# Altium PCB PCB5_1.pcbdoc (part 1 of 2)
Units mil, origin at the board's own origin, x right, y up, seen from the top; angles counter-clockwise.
Board outline 4312.83 x 4315.15 mil, 4 copper layers (Top Layer, Inner1, Inner2, Bottom Layer); 84 components, 70 nets, 244 pads, 79 vias.
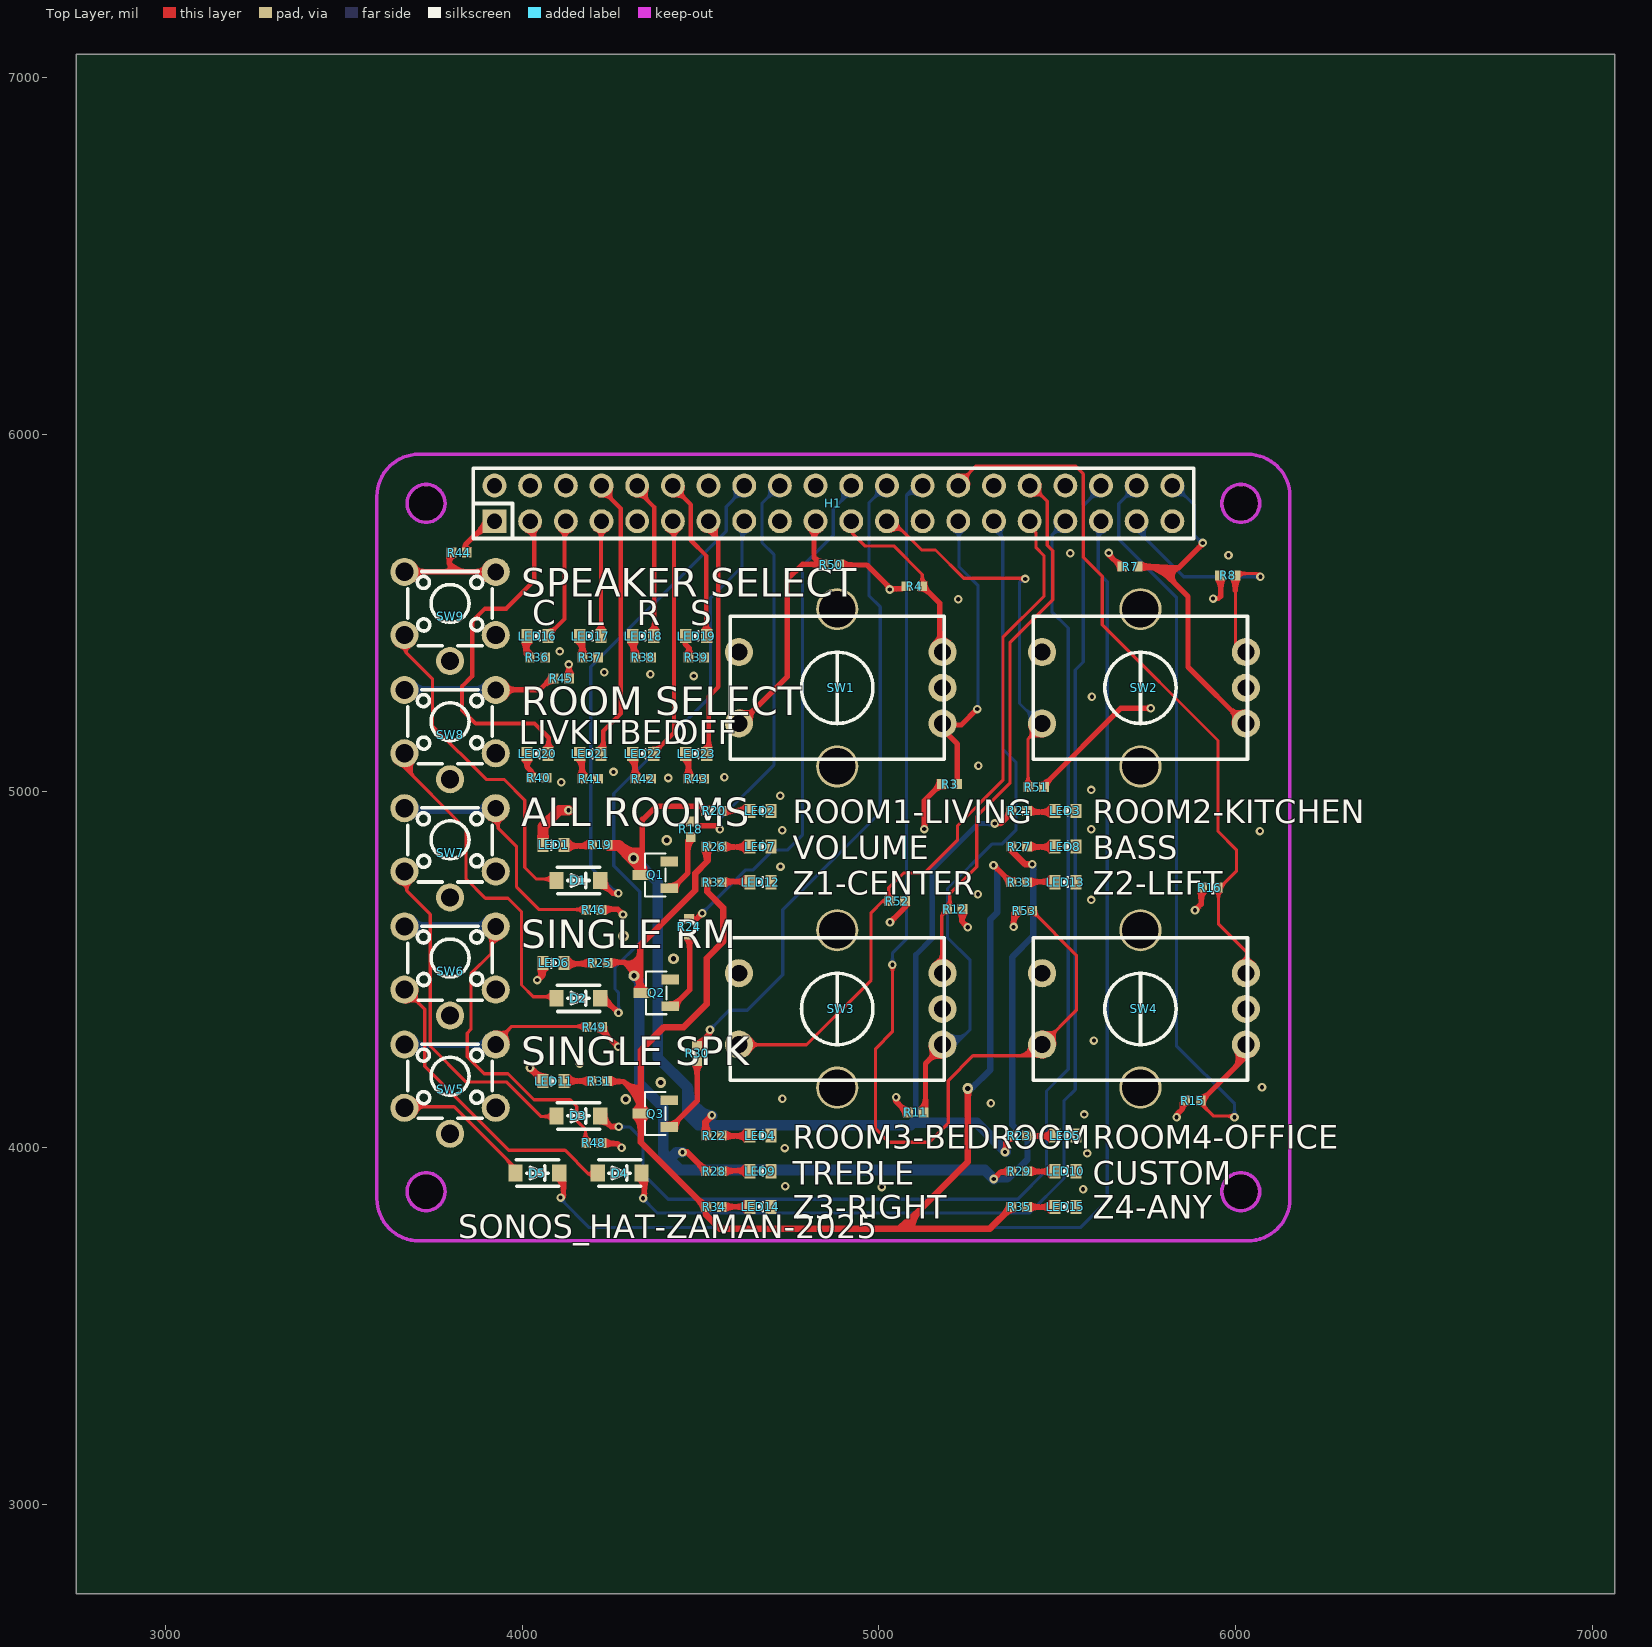
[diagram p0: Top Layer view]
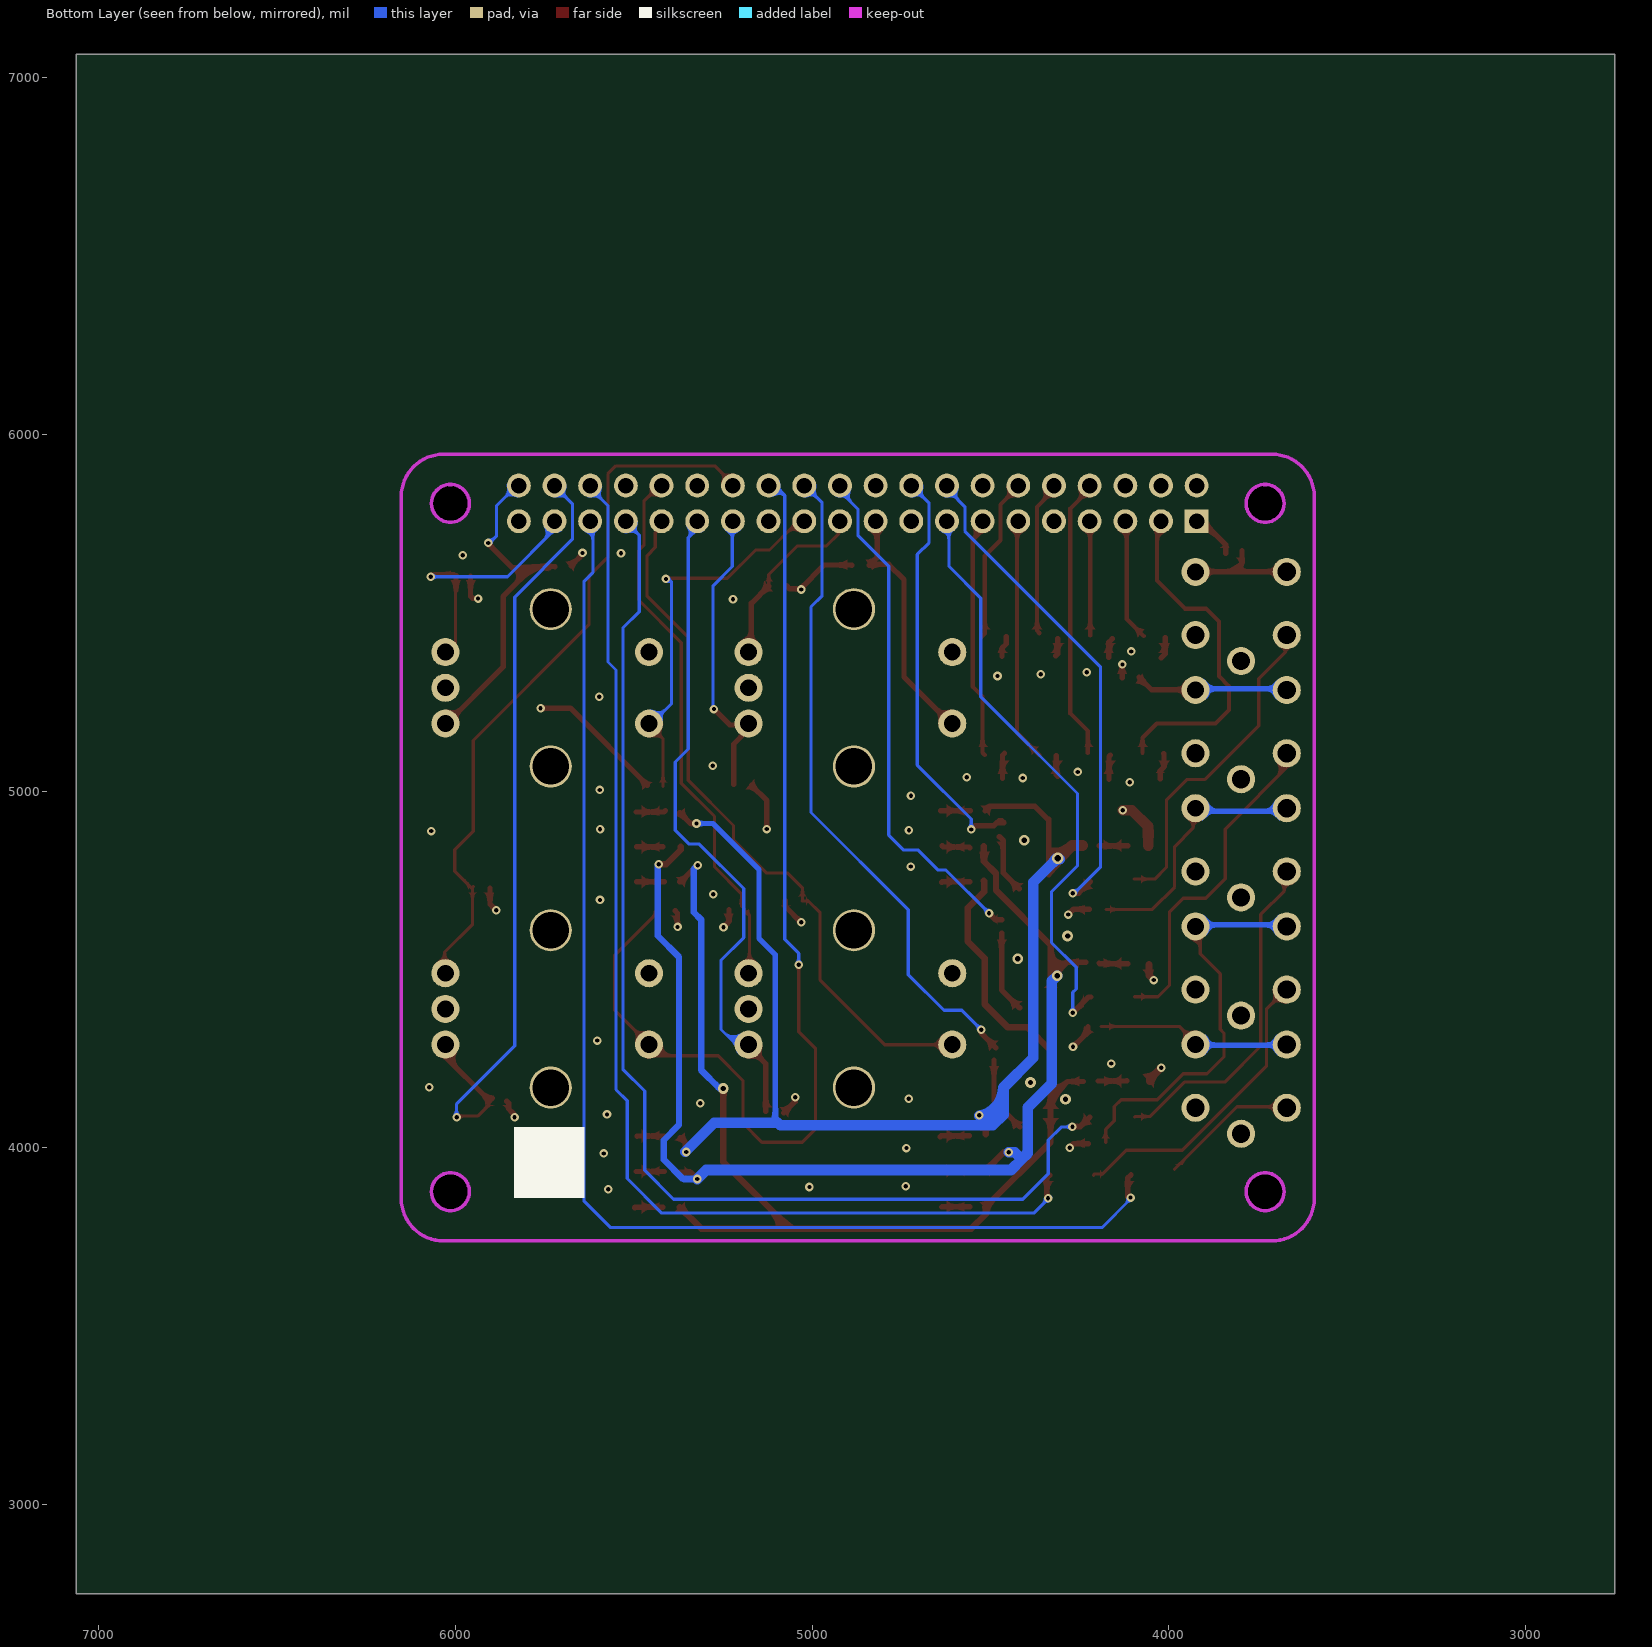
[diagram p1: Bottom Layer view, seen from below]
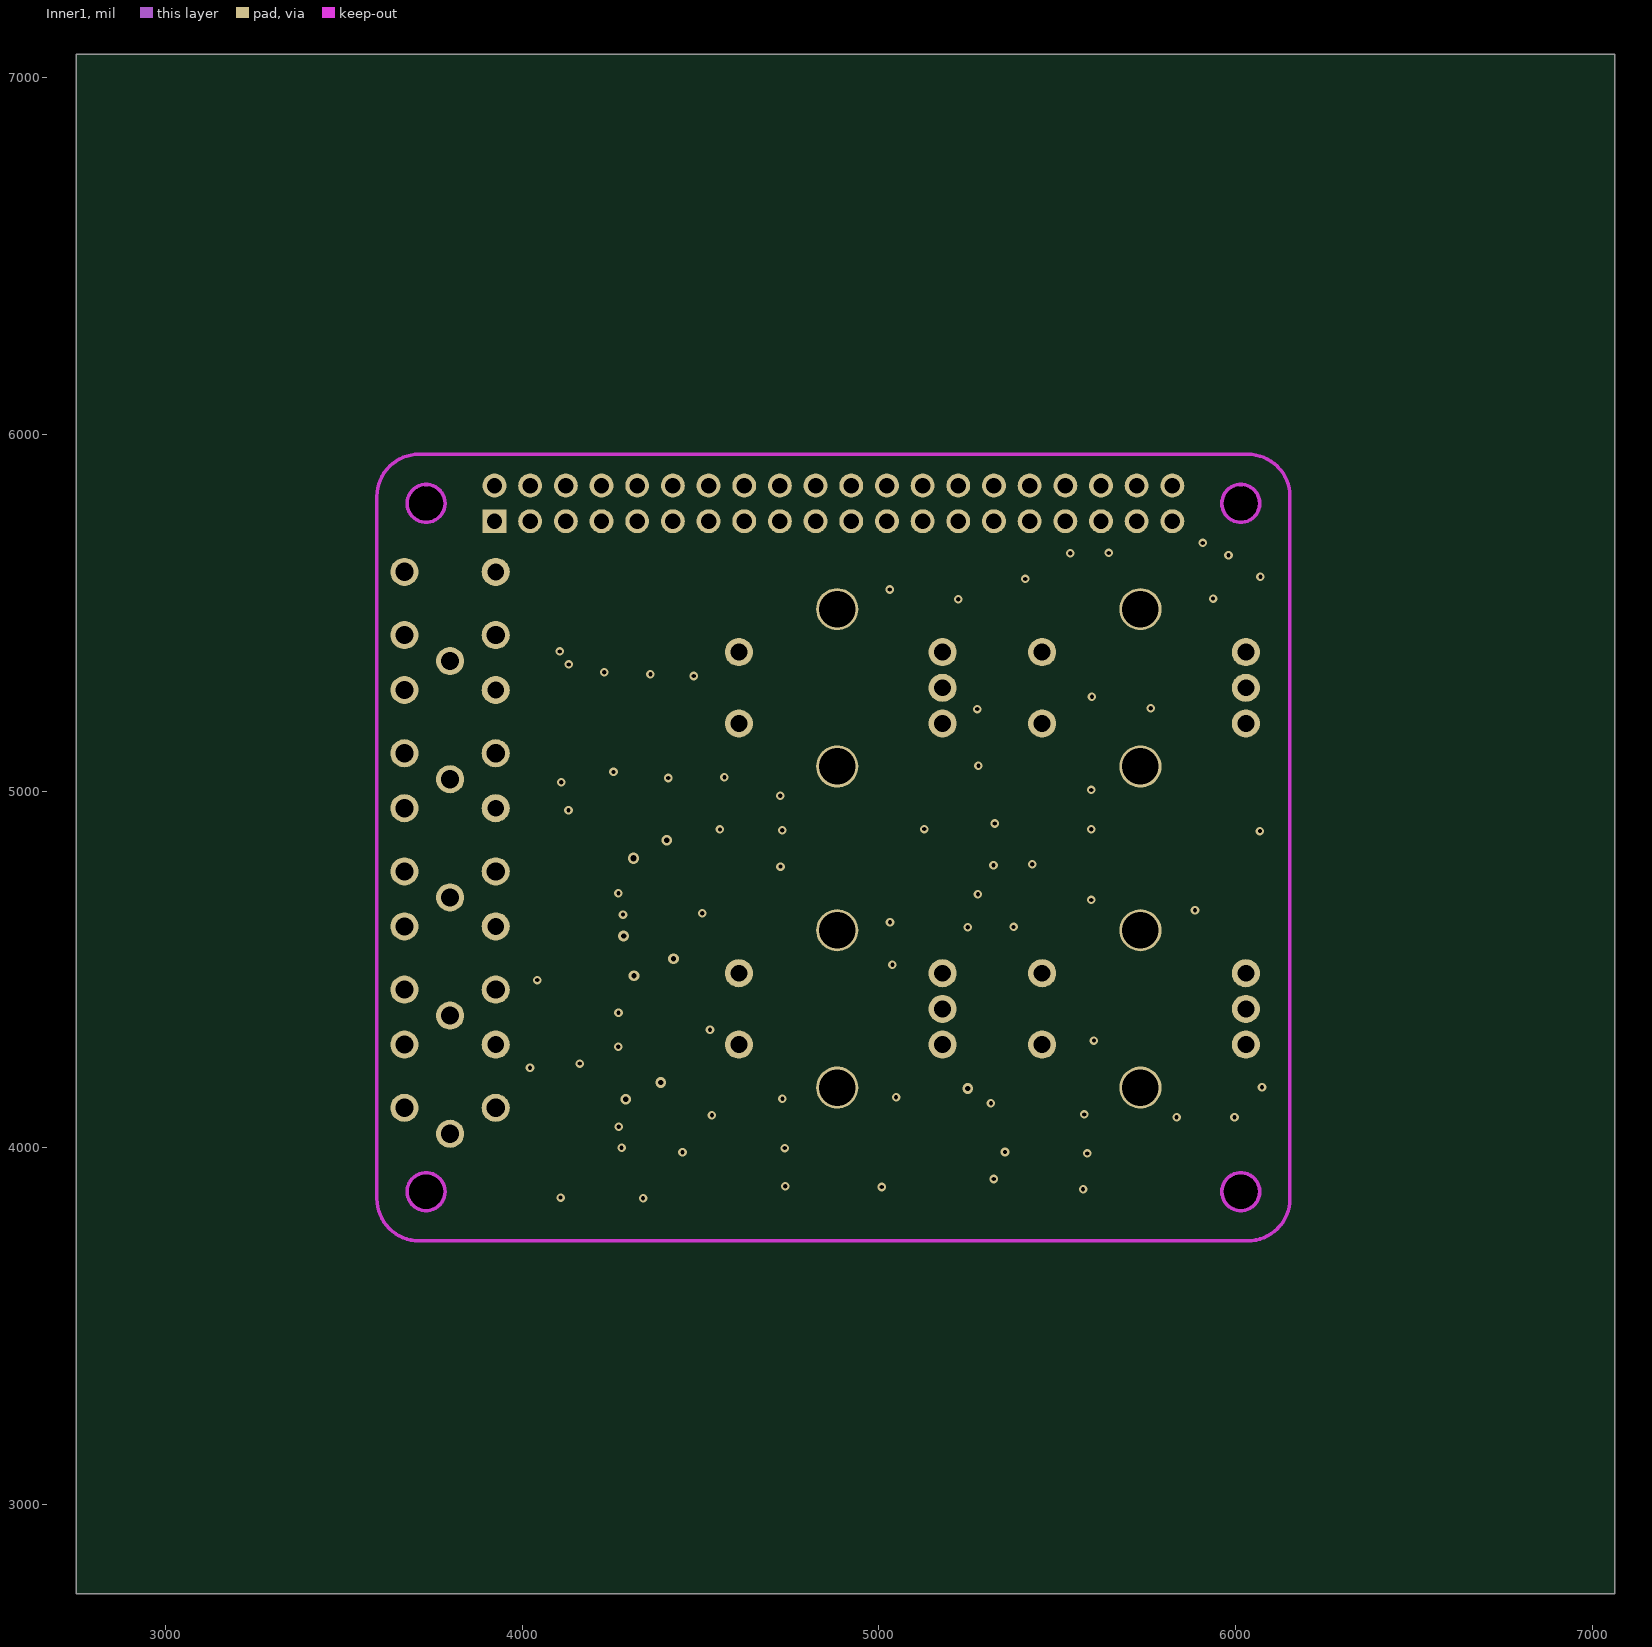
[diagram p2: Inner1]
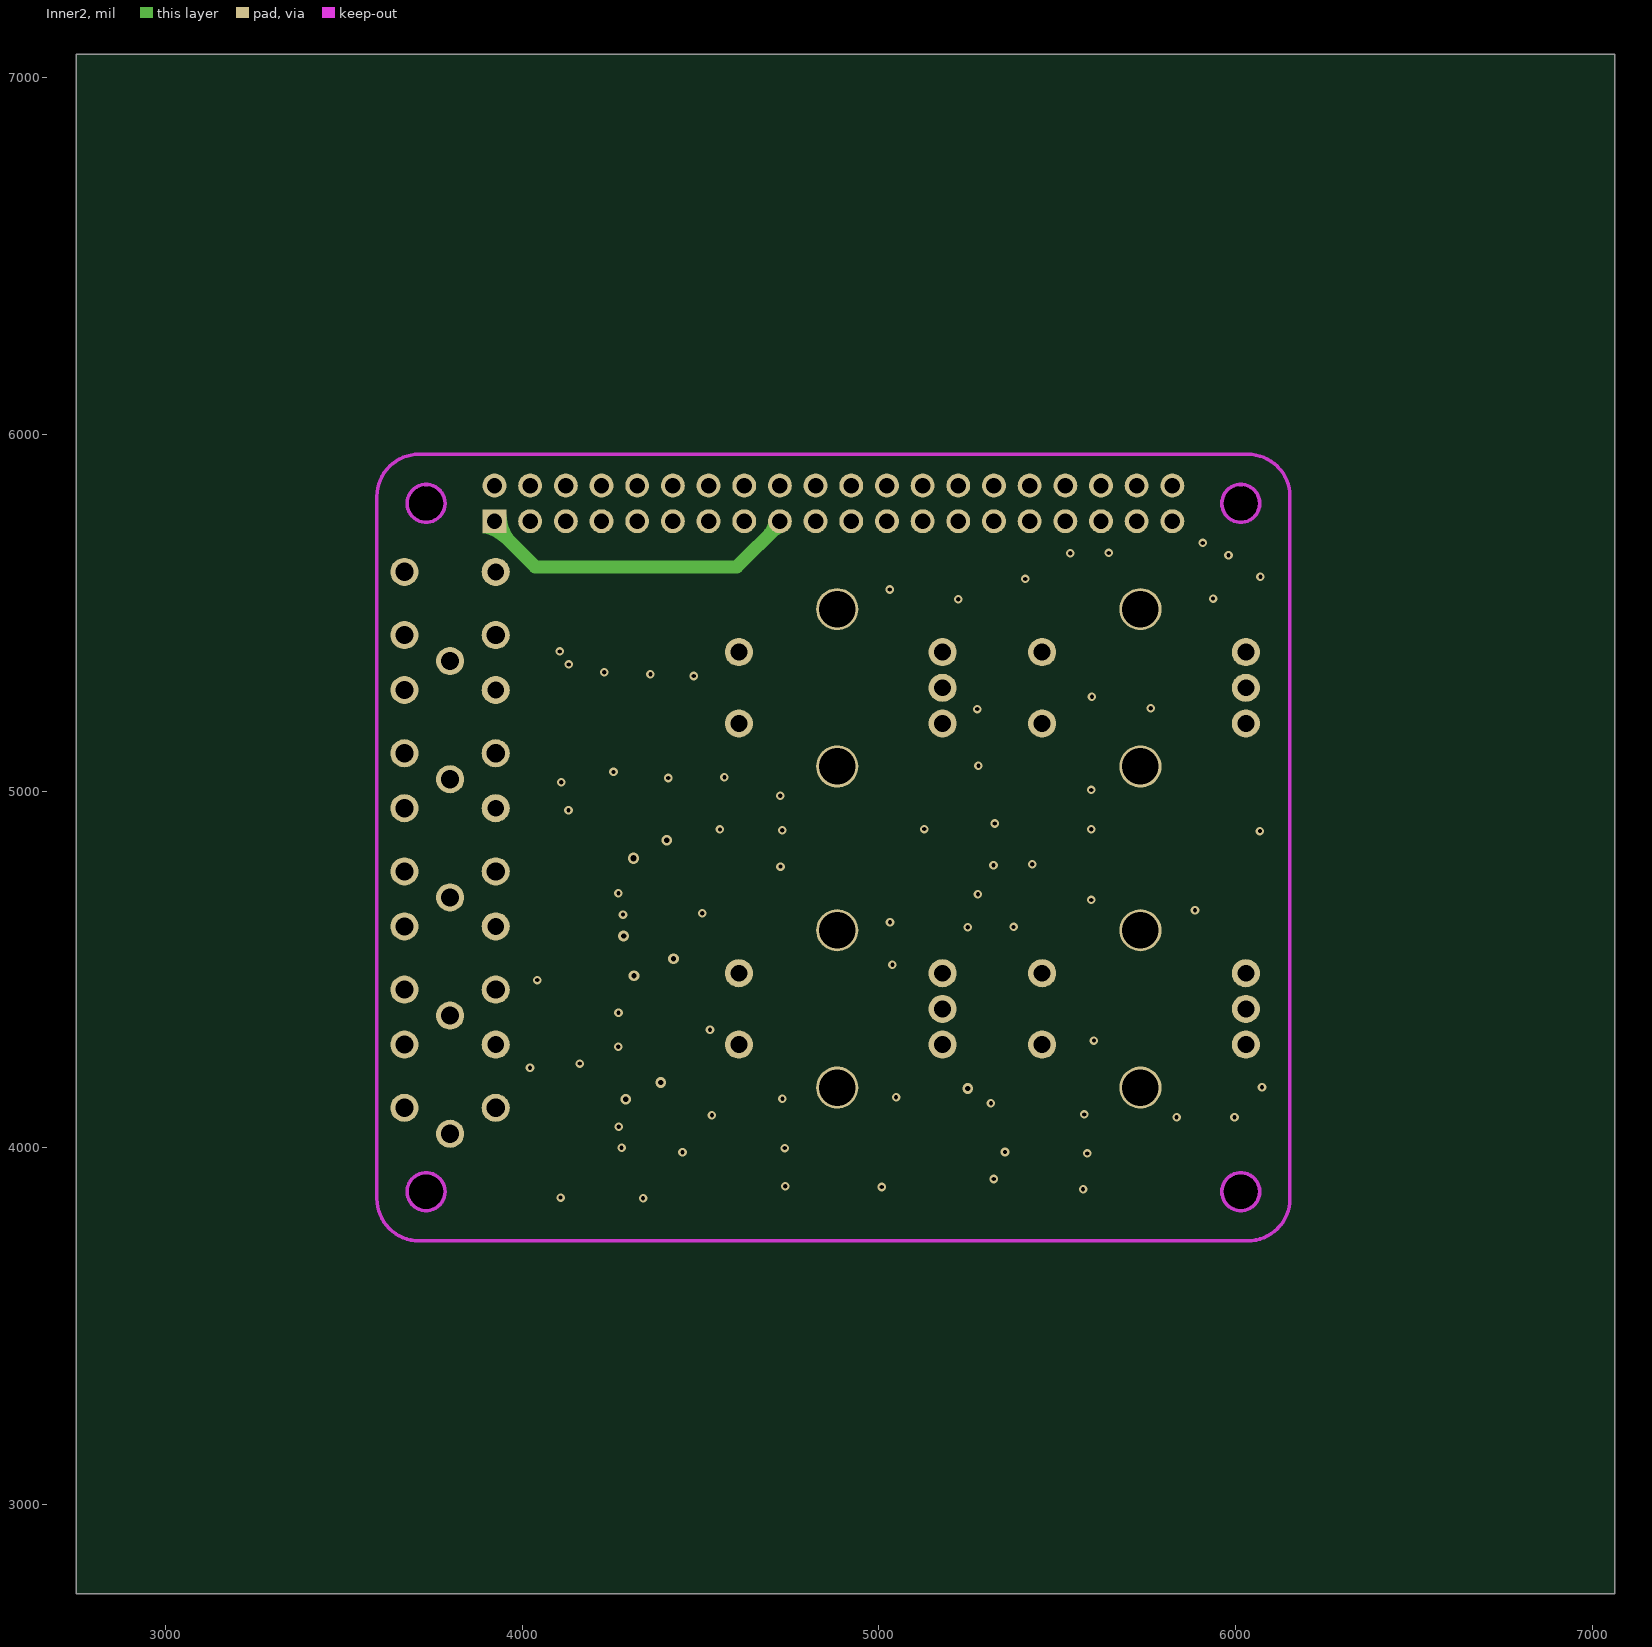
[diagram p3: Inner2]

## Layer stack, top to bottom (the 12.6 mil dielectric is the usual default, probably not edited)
Top Layer: signal copper (thickness not stored)
Dielectric: dielectric 12.6, FR-4, Dk 4.8
Inner1: signal copper (thickness not stored)
Dielectric: dielectric 12.6, FR-4, Dk 4.8
Inner2: signal copper (thickness not stored)
Dielectric: dielectric 12.6, FR-4, Dk 4.8
Bottom Layer: signal copper (thickness not stored)

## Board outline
7062.83,2750 2750,2750 2750,7065.15 7062.83,7065.15
cut-out: 3783.73,3877.07 ccw(c3730.58,3877.07) 3677.43,3877.07 ccw(c3730.58,3877.07)
cut-out: 3783.73,5806.2 ccw(c3730.58,5806.2) 3677.43,5806.2 ccw(c3730.58,5806.2)
cut-out: 6067.2,3877.07 ccw(c6014.05,3876.85) 5960.9,3877.07 ccw(c6014.05,3877.29)
cut-out: 6067.2,5806.2 ccw(c6014.05,5805.98) 5960.9,5806.2 ccw(c6014.05,5806.42)

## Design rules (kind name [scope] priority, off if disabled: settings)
BoardOutlineClearance copperThickness1oz [All] p0: genericclearance=10 ignorepadtopadclearanceinfootprint=FALSE except(0: Arc-SplitContinuation Track-SplitContinuation SMDPad-SplitContinuation THPad-SplitContinuation Via-SplitContinuation Fill-SplitContinuation Poly-SplitContinuation Region-SplitContinuation Text-SplitContinuation; 6: Track-CutoutEdge SMDPad-CutoutEdge THPad-CutoutEdge Via-CutoutEdge Region-CutoutEdge; 11.8: Track-OutlineEdge SMDPad-OutlineEdge THPad-OutlineEdge Via-OutlineEdge Fill-OutlineEdge Region-OutlineEdge Poly-OutlineEdge Text-OutlineEdge Fill-CutoutEdge)
BoardOutlineClearance copperThickness2oz [All] p0: genericclearance=10 ignorepadtopadclearanceinfootprint=FALSE except(0: Arc-SplitContinuation Track-SplitContinuation SMDPad-SplitContinuation THPad-SplitContinuation Via-SplitContinuation Fill-SplitContinuation Poly-SplitContinuation Region-SplitContinuation Text-SplitContinuation; 6: Track-CutoutEdge SMDPad-CutoutEdge THPad-CutoutEdge Via-CutoutEdge Region-CutoutEdge; 11.8: Track-OutlineEdge SMDPad-OutlineEdge THPad-OutlineEdge Via-OutlineEdge Fill-OutlineEdge Region-OutlineEdge Poly-OutlineEdge Text-OutlineEdge Fill-CutoutEdge)
Clearance copperThickness1oz [(InNet('GND') OR InNet('CLK_VOL') OR InNet('DT_VOL') OR InNet('+3.3V') OR InNet('+5V') OR InNet('DT_TREB') OR InNet('CLK_TREB') OR InNet('SW_BASS') OR InNet('DT_BASS') OR InNet('CLK_BASS') OR InNet('SW_TREB') OR InNet('SW_VOL') OR InNet('DT_EXTRA') OR InNet('CLK_EXTRA') OR InNet('SW_EXTRA') OR InNet('ROOM3_LED') OR InNet('ROOM4_LED') OR InNet('ALL_ROOM_LED') OR InNet('SINGLE_ROOM_LED') OR InNet('SINGLE_SPK_LED') OR InNet('SPK1_LED') OR InNet('SPK2_LED') OR InNet('SPK3_LED') OR InNet('SPK4_LED') OR InNet('ROOM1_LED') OR InNet('ROOM2_LED') OR InNet('$2N567') OR InNet('$2N579') OR InNet('$2N581') OR InNet('$2N585') OR InNet('$2N583') OR InNet('$2N1097') OR InNet('$2N1109') OR InNet('$2N1111') OR InNet('$2N1113') OR InNet('$2N1115') OR InNet('$2N1627') OR InNet('$2N1639') OR InNet('$2N1641') OR InNet('$2N1643') OR InNet('$2N1645') OR InNet('$2N2275') OR InNet('$2N2279') OR InNet('$2N2284') OR InNet('$2N2289') OR InNet('$2N2294') OR InNet('$2N2299') OR InNet('$2N2307') OR InNet('$2N2312') OR InNet('$2N553') OR InNet('$2N557') OR InNet('$2N1083') OR InNet('$2N1087') OR InNet('$2N1613') OR InNet('$2N1617') OR InNet('SW_ALL_ROOM') OR InNet('SW_SINGLE_ROOM') OR InNet('SW_SINGLE_SPK') OR InNet('SW_CHG_SPK') OR InNet('SW_CHG_ROOM') OR InNet('$2N6344') OR InNet('$2N6573') OR InNet('$2N6348') OR InNet('$2N6576') OR InNet('$2N6353') OR InNet('$2N6578') OR InNet('$2N6363') OR InNet('$2N6582') OR InNet('$2N6358') OR InNet('$2N6580'))] p1: gap=7 ignorepadtopadclearanceinfootprint=FALSE except(4: Track-Track; 6: Track-SMDPad SMDPad-SMDPad Track-THPad SMDPad-THPad THPad-THPad Track-Via SMDPad-Via THPad-Via Via-Via SMDPad-Fill THPad-Fill Via-Fill Fill-Fill Track-Region SMDPad-Region THPad-Region Via-Region Region-Region Track-Poly SMDPad-Poly THPad-Poly Via-Poly Fill-Poly Region-Poly Poly-Poly Track-Text SMDPad-Text THPad-Text Via-Text Fill-Text Region-Text Poly-Text Text-Text; 6.9: Track-Hole SMDPad-Hole THPad-Hole Via-Hole Fill-Hole Region-Hole Poly-Hole Text-Hole Sheet-Hole; 11.8: Track-Fill Fill-Region Track-Sheet SMDPad-Sheet THPad-Sheet Via-Sheet Fill-Sheet Region-Sheet Poly-Sheet Text-Sheet)
Clearance copperThickness2oz [All] p1: gap=7 ignorepadtopadclearanceinfootprint=FALSE except(6: Track-SMDPad SMDPad-SMDPad Track-THPad SMDPad-THPad THPad-THPad Track-Via SMDPad-Via THPad-Via Via-Via SMDPad-Fill THPad-Fill Via-Fill Fill-Fill Track-Region SMDPad-Region THPad-Region Via-Region Region-Region Track-Poly SMDPad-Poly THPad-Poly Via-Poly Fill-Poly Region-Poly Poly-Poly Track-Text SMDPad-Text THPad-Text Via-Text Fill-Text Region-Text Poly-Text Text-Text; 6.9: Track-Hole SMDPad-Hole THPad-Hole Via-Hole Fill-Hole Region-Hole Poly-Hole Text-Hole Sheet-Hole; 8: Track-Track; 11.8: Track-Fill Fill-Region Track-Sheet SMDPad-Sheet THPad-Sheet Via-Sheet Fill-Sheet Region-Sheet Poly-Sheet Text-Sheet)
DiffPairsRouting differentialPair [All] p1: maxuncoupledlength=10 minlimit=6 maxlimit=6 mostfreqgap=6 toplayer_minwidth=5 toplayer_prefwidth=10 toplayer_maxwidth=100 bottomlayer_minwidth=5 bottomlayer_prefwidth=10 bottomlayer_maxwidth=100 midlayer1_minwidth=5 midlayer1_prefwidth=10 midlayer1_maxwidth=100 midlayer2_minwidth=5 midlayer2_prefwidth=10 midlayer2_maxwidth=100
PasteMaskExpansion pasteMaskExpansion [All] p1: expansion=0
PlaneConnect innerPlane [All] p1: planeconnectstyle=Relief reliefexpansion=20 reliefentries=4 reliefconductorwidth=10 reliefairgap=10
PolygonConnect copperRegion [All] p1: connectstyle=Direct reliefentries=4 reliefconductorwidth=10 polygonreliefangle="90 Angle" airgapwidth=10
PolygonConnect copperRegion1 [All] p1: connectstyle=Relief reliefentries=4 reliefconductorwidth=10 polygonreliefangle="90 Angle" airgapwidth=10
PolygonConnect copperRegion2 [All] p1: connectstyle=Direct reliefentries=4 reliefconductorwidth=10 polygonreliefangle="90 Angle" airgapwidth=10
RoutingVias viaSize [All] p1: viastyle="Through Hole" holewidth=12 minholewidth=11.8 maxholewidth=248 width=24 minwidth=19.7 maxwidth=393.7
SolderMaskExpansion solderMaskExpansion [All] p1: useseparateexpansions=TRUE expansion=2 expansionbottom=2
Width copperThickness1oz [All] p1: maxlimit=100 minlimit=5 preferedwidth=15
Width copperThickness2oz [All] p1: maxlimit=100 minlimit=8 preferedwidth=10

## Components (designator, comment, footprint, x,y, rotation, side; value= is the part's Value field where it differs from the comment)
D1 "SM4007PL_C64898" SOD-123F_L2.8-W1.8-LS3.7-RD 4157.79,4749.27 r180 top
D2 "SM4007PL_C64898" SOD-123F_L2.8-W1.8-LS3.7-RD 4157.79,4419.27 r180 top
D3 "SM4007PL_C64898" SOD-123F_L2.8-W1.8-LS3.7-RD 4157.79,4089.28 r180 top
D4 "SM4007PL_C64898" SOD-123F_L2.8-W1.8-LS3.7-RD 4272.79,3929.28 r180 top locked
D5 "SM4007PL_C64898" SOD-123F_L2.8-W1.8-LS3.7-RD 4042.79,3929.28 r180 top locked
H1 "2.54-2*20P母长PC104" HDR-TH_40P-P2.54-V-F-R2-C20-S2.54-2 4872.32,5806.2 r0 top locked
LED1 "KT-0603R" LED0603-RD 4087.79,4849.27 r180 top
LED2 "KT-0603R" LED0603-RD 4667.79,4944.27 r0 top locked
LED3 "KT-0603R" LED0603-RD 5522.79,4944.27 r0 top locked
LED4 "KT-0603R" LED0603-RD 4667.79,4034.28 r0 top locked
LED5 "KT-0603R" LED0603-RD 5522.79,4034.28 r0 top locked
LED6 "KT-0603R" LED0603-RD 4087.79,4518.07 r180 top
LED7 "KT-0603R" LED0603-RD 4667.79,4844.27 r0 top locked
LED8 "KT-0603R" LED0603-RD 5522.79,4844.27 r0 top locked
LED9 "KT-0603R" LED0603-RD 4667.79,3934.28 r0 top locked
LED10 "KT-0603R" LED0603-RD 5522.79,3934.28 r0 top locked
LED11 "KT-0603R" LED0603-RD 4087.79,4186.77 r180 top
LED12 "KT-0603R" LED0603-RD 4667.79,4744.27 r0 top locked
LED13 "KT-0603R" LED0603-RD 5522.79,4744.27 r0 top locked
LED14 "KT-0603R" LED0603-RD 4667.79,3834.28 r0 top locked
LED15 "KT-0603R" LED0603-RD 5522.79,3834.28 r0 top locked
LED16 "KT-0603R" LED0603-RD 4042.79,5434.27 r0 top
LED17 "KT-0603R" LED0603-RD 4191.12,5434.27 r0 top
LED18 "KT-0603R" LED0603-RD 4339.45,5434.27 r0 top
LED19 "KT-0603R" LED0603-RD 4487.79,5434.27 r0 top
LED20 "KT-0603R" LED0603-RD 4042.79,5104.27 r0 top
LED21 "KT-0603R" LED0603-RD 4191.09,5104.27 r0 top
LED22 "KT-0603R" LED0603-RD 4339.49,5104.27 r0 top
LED23 "KT-0603R" LED0603-RD 4487.79,5104.27 r0 top
Q1 "MMBT2222A 1P" SOT-23-3_L2.9-W1.3-P1.90-LS2.4-BR 4372.79,4764.72 r0 top
Q2 "MMBT2222A 1P" SOT-23-3_L2.9-W1.3-P1.90-LS2.4-BR 4375.39,4434.27 r0 top
Q3 "MMBT2222A 1P" SOT-23-3_L2.9-W1.3-P1.90-LS2.4-BR 4372.79,4095.98 r0 top
R3 "0402WGF1002TCE" C0402 5197.79,5019.27 r0 top locked
R4 "0402WGF1002TCE" C0402 5099.24,5573.78 r0 top
R7 "0402WGF1002TCE" C0402 5703.81,5629.27 r180 top
R8 "0402WGF1002TCE" C0402 5977.79,5604.27 r180 top
R11 "0402WGF1002TCE" C0402 5102.79,4099.27 r0 top
R12 "0402WGF1002TCE" C0402 5212.79,4669.27 r180 top
R15 "0402WGF1002TCE" C0402 5880.05,4132.5 r180 top
R16 "0402WGF1002TCE" C0402 5927.79,4729.27 r180 top
R18 "ERJ2RKF3900X" C0402 4472.38,4892.77 r270 top
R19 "CRCW0402200RFKEDHP" C0402 4217.79,4849.27 r180 top
R20 "CRCW0402200RFKEDHP" C0402 4537.79,4944.27 r0 top
R21 "CRCW0402200RFKEDHP" C0402 5392.79,4944.27 r0 top
R22 "CRCW0402200RFKEDHP" C0402 4537.79,4034.28 r0 top
R23 "CRCW0402200RFKEDHP" C0402 5392.79,4034.28 r0 top
R24 "ERJ2RKF3900X" C0402 4467.79,4619.27 r270 top
R25 "CRCW0402200RFKEDHP" C0402 4217.79,4518.07 r180 top
R26 "CRCW0402200RFKEDHP" C0402 4537.79,4844.27 r0 top
R27 "CRCW0402200RFKEDHP" C0402 5392.79,4844.27 r0 top
R28 "CRCW0402200RFKEDHP" C0402 4537.79,3934.28 r0 top
R29 "CRCW0402200RFKEDHP" C0402 5392.79,3934.28 r0 top
R30 "ERJ2RKF3900X" C0402 4490.25,4264.5 r270 top
R31 "CRCW0402200RFKEDHP" C0402 4216.41,4186.77 r180 top
R32 "CRCW0402200RFKEDHP" C0402 4537.79,4744.27 r0 top
R33 "CRCW0402200RFKEDHP" C0402 5392.79,4744.27 r0 top
R34 "CRCW0402200RFKEDHP" C0402 4537.79,3834.28 r0 top
R35 "CRCW0402200RFKEDHP" C0402 5392.79,3834.28 r0 top
R36 "0402WGF1200TCE" C0402 4042.79,5374.27 r180 top
R37 "0402WGF1200TCE" C0402 4191.09,5374.27 r180 top
R38 "0402WGF1200TCE" C0402 4339.49,5374.27 r180 top
R39 "0402WGF1200TCE" C0402 4487.79,5374.27 r180 top
R40 "0402WGF1200TCE" C0402 4046.75,5037.01 r180 top
R41 "0402WGF1200TCE" C0402 4191.09,5034.27 r180 top
R42 "0402WGF1200TCE" C0402 4339.49,5034.27 r180 top
R43 "0402WGF1200TCE" C0402 4487.79,5034.27 r180 top
R44 "0402WGF1001TCE" C0402 3823.07,5668.31 r180 top
R45 "0402WGF1001TCE" C0402 4109.81,5315.47 r180 top
R46 "0402WGF1001TCE" C0402 4200.61,4666.76 r180 top
R48 "0402WGF1001TCE" C0402 4200.42,4013.5 r180 top
R49 "0402WGF1001TCE" C0402 4202.57,4338.22 r180 top
R50 "0402WGF1001TCE" C0402 4866.66,5634.53 r0 top
R51 "0402WGF1001TCE" C0402 5440.47,5010.84 r0 top
R52 "0402WGF1001TCE" C0402 5051.58,4691.56 r0 top
R53 "0402WGF1001TCE" C0402 5407.79,4664.27 r180 top
SW1 "PEC12R-4230F-S0024" SW-TH_PEC12R-4230F-S0024 4892.79,5289.27 r90 top locked
SW2 "PEC12R-4230F-S0024" SW-TH_PEC12R-4230F-S0024 5742.79,5289.27 r90 top locked
SW3 "PEC12R-4230F-S0024" SW-TH_PEC12R-4230F-S0024 4892.79,4389.27 r90 top locked
SW4 "PEC12R-4230F-S0024" SW-TH_PEC12R-4230F-S0024 5742.79,4389.27 r90 top locked
SW5 "SKHHQVA010" SW-TH_5P-L6.0-W6.0-P4.50-LS6.5 3797.79,4164.27 r0 top locked
SW6 "SKHHQVA010" SW-TH_5P-L6.0-W6.0-P4.50-LS6.5 3797.79,4495.52 r0 top locked
SW7 "SKHHQVA010" SW-TH_5P-L6.0-W6.0-P4.50-LS6.5 3797.79,4826.77 r0 top locked
SW8 "SKHHQVA010" SW-TH_5P-L6.0-W6.0-P4.50-LS6.5 3797.79,5158.02 r0 top locked
SW9 "SKHHQVA010" SW-TH_5P-L6.0-W6.0-P4.50-LS6.5 3797.79,5489.27 r0 top locked

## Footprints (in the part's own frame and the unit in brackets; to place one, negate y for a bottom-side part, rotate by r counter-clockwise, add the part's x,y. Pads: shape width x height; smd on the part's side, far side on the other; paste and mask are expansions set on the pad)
C0402 [mm]
  rect 0.7x0.7 smd: 1(-0.55,0) 2(0.55,0)
HDR-TH_40P-P2.54-V-F-R2-C20-S2.54-2 [mm]
  rect 1.7x1.7 hole 1.1: 1(-24.13,-1.27)
  round 1.7 hole 1.1: 2(-24.13,1.27) 3(-21.59,-1.27) 4(-21.59,1.27) 5(-19.05,-1.27) 6(-19.05,1.27) 7(-16.51,-1.27) 8(-16.51,1.27) 9(-13.97,-1.27) 10(-13.97,1.27) 11(-11.43,-1.27) 12(-11.43,1.27) 13(-8.89,-1.27) 14(-8.89,1.27) 15(-6.35,-1.27) 16(-6.35,1.27) 17(-3.81,-1.27) 18(-3.81,1.27) 19(-1.27,-1.27) 20(-1.27,1.27) 21(1.27,-1.27) 22(1.27,1.27) 23(3.81,-1.27) 24(3.81,1.27) 25(6.35,-1.27) 26(6.35,1.27) 27(8.89,-1.27) 28(8.89,1.27) 29(11.43,-1.27) 30(11.43,1.27) 31(13.97,-1.27) 32(13.97,1.27) 33(16.51,-1.27) 34(16.51,1.27) 35(19.05,-1.27) 36(19.05,1.27) 37(21.59,-1.27) 38(21.59,1.27) 39(24.13,-1.27) 40(24.13,1.27)
  silkscreen extent -25.65,-2.5 25.65,2.5
LED0603-RD [mm]
  rect 0.8x1 smd: 1(-0.75,0) 2(0.75,0)
  silkscreen extent -0.18,-0.32 0.17,0.36
SOD-123F_L2.8-W1.8-LS3.7-RD [mm]
  rect 1x1.2 smd: 1(-1.55,0) 2(1.55,0)
  silkscreen extent -1.52,-0.93 1.49,0.95
SOT-23-3_L2.9-W1.3-P1.90-LS2.4-BR [mm]
  rect 1.25x0.7 smd: 1(1,-0.95) 2(1,0.95) 3(-1,0)
  silkscreen extent -0.73,-1.53 0.73,1.53
SW-TH_5P-L6.0-W6.0-P4.50-LS6.5 [mm]
  round 2 hole 1.3: 1(-3.25,3.175) 3(-3.25,-1.325) 4(3.25,-1.325) 5(0.001,-3.175)
  round 2 hole 1.199: 2(3.25,3.175)
  silkscreen extent -3,-2.07 3,3.2
SW-TH_PEC12R-4230F-S0024 [mm]
  round 2 hole 1.2: 1(-2.54,7.25) 2(2.54,7.25) A(-2.54,-7.25) B(2.54,-7.25) C(0,-7.25)
  round 3 hole 2.6: 6(-5.601,0.25) 7(5.601,0.25)
  silkscreen extent -5.08,-7.37 5.08,7.87

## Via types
v1: diameter 24.02, hole 12.01, Top Layer to Bottom Layer, 69 vias
v2: diameter 30, hole 15, Top Layer to Bottom Layer, 7 vias
v3: diameter 24, hole 12, Top Layer to Bottom Layer, 2 vias
v4: diameter 32, hole 18, Top Layer to Bottom Layer, 1 vias

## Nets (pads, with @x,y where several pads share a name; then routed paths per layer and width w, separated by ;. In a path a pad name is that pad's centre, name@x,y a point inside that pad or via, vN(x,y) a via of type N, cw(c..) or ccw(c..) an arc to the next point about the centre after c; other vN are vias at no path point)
$2N553: Q1.1 R18.2 | length 169.5
  Top Layer w15: Q1.1@4419.54,4725.63 4464.38,4770.47 4464.38,4860.98 R18.2@4475.37,4871.97
$2N557: Q1.3 R19.1 R20.1 R21.1 R22.1 R23.1 | length 3385.2
  Top Layer w15: Q1.3@4336.58,4764.86 4336.58,4781.86 4336.58,4920.61 ; 4338.96,4920.61 4375.55,4957.2 4502.22,4957.2 R20.1@4515.59,4943.83 ; v1(5324.25,4909.02) 5341.61,4909.02 R21.1@5371.54,4938.95 ; v1@5355.72,3988.03 5355.72,4014.07 R23.1@5369.8,4028.14
  Top Layer w18: R22.1@4513.55,4037.99 4513.55,4072.48 v1@4532.55,4091.48
  Top Layer w30: R19.1@4242.64,4847.19 4271.26,4847.19 4336.58,4781.86
  Bottom Layer w15: 5103.1,4067.83 5103.1,4070.15 5103.1,4540.98 5149.01,4586.9 5149.01,4779.75 5278.29,4909.02 v1(5324.25,4909.02)
  Bottom Layer w30: v4@4307.05,4808.83 v4@4309.49,4811.27 ; v4@4313.45,4811.27 4380.07,4744.65 4380.07,4252.76 4463.81,4169.01 4463.81,4092.84 4493.81,4062.84 5089.06,4062.84 5096.37,4070.15 5103.1,4070.15 5274.37,4070.15 v1@5355.74,3988.77 ; 4473.04,4090.06 v1@4532.15,4090.06
  other v1: 5353.14,3988.27 4531.85,4091.48
  other v4: 4311.99,4811.91
$2N567: LED1.1 R19.2 | length 79.2
  Top Layer w15: LED1.1@4115.97,4846.14 R19.2@4195.14,4846.14
$2N579: LED2.1 R20.2 | length 82.8
  Top Layer w15: R20.2@4556.64,4944.39 4557.11,4944.86 LED2.1@4639.21,4944.86
$2N581: LED3.1 R21.2 | length 84.1
  Top Layer w15: R21.2@5411.3,4945.56 5415.52,4941.34 LED3.1@5493.64,4941.34
$2N583: LED4.1 R22.2 | length 82.8
  Top Layer w15: R22.2@4559.92,4033.43 4638.74,4033.43 LED4.1@4641.55,4030.61
$2N585: LED5.1 R23.2 | length 76.3
  Top Layer w15: R23.2@5415.17,4032.9 5490.47,4032.9 LED5.1@5491.17,4032.19
$2N1083: Q2.1 R24.2 | length 231
  Top Layer w15: Q2.1@4418.48,4392.07 4469.15,4442.73 R24.2@4469.15,4602.13
$2N1087: Q2.3 R25.1 R26.1 R27.1 R28.1 R29.1 | length 3355
  Top Layer w15: R25.1@4233.14,4519.96 4286.27,4519.96 4331.1,4475.13 Q2.3@4331.1,4433.41 ; v1(5321.9,3912.61) 5341.03,3931.73 R29.1@5370.5,3931.73
  Top Layer w18: 4331.1,4475.13 4331.1,4567.81 4484.88,4721.59 4484.88,4769.09 4518.99,4803.2 R26.1@4518.99,4845.43 ; v1(4449.28,3987.17) 4463.04,3987.17 R28.1@4511.44,3938.77 ; R27.1@5368.72,4844.18 5368.72,4835.12 5409.48,4794.36 v1(5429.96,4794.36)
  Bottom Layer w18: v1(5321.9,3912.61) 5361.87,3912.61 5416.25,3966.99 5416.25,4021.28 5373.32,4064.21 5373.32,4534.66 5432.85,4594.19 5432.85,4791.47 v1(5429.96,4794.36)
  Bottom Layer w30: v2(4313.28,4482.45) 4328.32,4467.42 4328.32,4180.31 4395.65,4112.98 4395.65,3984.85 4398.12,3982.37 ; 4398.12,3984.8 4398.12,3982.37 ; v1(4449.28,3987.17) 4432.43,3987.17 4412.88,3967.62 ; v1(5321.9,3912.61) 5296.61,3937.9 4442.59,3937.9 4412.88,3967.62 ; 4398.12,3982.37 4412.88,3967.62
$2N1097: LED6.1 R25.2 | length 81.1
  Top Layer w15: LED6.1@4115.97,4515.74 4194.08,4515.74 R25.2@4196.19,4517.85
$2N1109: LED7.1 R26.2 | length 79.9
  Top Layer w15: R26.2@4558.07,4840.91 4560.24,4843.08 4632.61,4843.08 LED7.1@4635.77,4846.25
$2N1111: LED8.1 R27.2 | length 73.9
  Top Layer w15: R27.2@5418.34,4843.52 LED8.1@5492.23,4843.52
$2N1113: LED9.1 R28.2 | length 80.8
  Top Layer w15: R28.2@4557.57,3934.44 4558.98,3935.84 LED9.1@4637.8,3935.84
$2N1115: LED10.1 R29.2 | length 78.1
  Top Layer w15: R29.2@5415.17,3933.67 LED10.1@5493.28,3933.67
$2N1613: Q3.1 R30.2 | length 217
  Top Layer w15: Q3.1@4417.42,4058.51 4490.26,4131.34 R30.2@4490.26,4245.34
$2N1617: Q3.3 R31.1 R32.1 R33.1 R34.1 R35.1 | length 3372
  Top Layer w15: R31.1@4239.78,4186.04 4284.11,4186.04 4331.97,4138.18 ; v1(5320.93,4792.33) 5367.13,4746.13 R33.1@5371.54,4746.13
  Top Layer w18: 4331.97,4015.74 4331.97,4138.18 4331.97,4273.81 ; 4332.16,4015.74 R34.1@4514.77,3833.13 ; 4333.02,4273.81 4397.64,4338.44 4452.53,4338.44 4516.92,4402.83 4516.92,4531.61 4563.62,4578.3 4563.62,4672.34 4518.33,4717.62 4518.33,4747.45 R32.1@4518.84,4747.96 ; R34.1@4513.77,3831.3 4513.77,3813.7 4553.88,3773.59 5311.25,3773.59 R35.1@5371.42,3833.76 ; 5065.78,3777.03 5249.04,3960.3 v2(5249.04,4166.08)
  Bottom Layer w18: v2(5249.04,4166.08) 5249.87,4166.91 5260.37,4166.91 5311.47,4218 5311.47,4639.89 5332.05,4660.47 5332.05,4781.22 v1(5320.93,4792.33)
  other v2: 4289.89,4135.91
$2N1627: LED11.1 R31.2 | length 80.5
  Top Layer w15: LED11.1@4118.74,4188.15 4119.44,4187.44 R31.2@4198.96,4187.44
$2N1639: LED12.1 R32.2 | length 78.5
  Top Layer w15: R32.2@4558.54,4746.14 4635.01,4746.14 LED12.1@4636.42,4744.74
$2N1641: LED13.1 R33.2 | length 78.4
  Top Layer w15: R33.2@5414.12,4746.41 5414.82,4745.7 LED13.1@5492.23,4745.7
$2N1643: LED14.1 R34.2 | length 78.1
  Top Layer w15: R34.2@4558.86,3834.74 4636.27,3834.74 LED14.1@4636.74,3834.27
$2N1645: LED15.1 R35.2 | length 80.1
  Top Layer w15: R35.2@5417.99,3833.75 5496.1,3833.75 LED15.1@5497.51,3832.34
$2N2275: LED16.1 R36.2 | length 61.9
  Top Layer w15: LED16.1@4010.73,5430.08 4010.73,5384.11 R36.2@4021.99,5372.85
$2N2279: LED17.1 R37.2 | length 55
  Top Layer w15: LED17.1@4158.98,5426.33 4168.37,5416.95 R37.2@4168.37,5375.19
$2N2284: LED18.1 R38.2 | length 50.5
  Top Layer w15: LED18.1@4312.16,5427.38 4312.16,5384.22 R38.2@4317.32,5379.06
$2N2289: LED19.1 R39.2 | length 59.7
  Top Layer w15: LED19.1@4456.19,5432.55 4456.19,5412.37 4467.91,5400.64 R39.2@4467.91,5377.66
$2N2294: LED20.1 R40.2 | length 75.7
  Top Layer w15: LED20.1@4014.97,5105.15 4014.04,5104.22 4014.04,5067.15 4024.83,5056.36 R40.2@4024.83,5034.31
$2N2299: LED21.1 R41.2 | length 70.2
  Top Layer w15: LED21.1@4163.69,5100.93 4167.92,5096.71 R41.2@4167.92,5032.44
$2N2307: LED22.1 R42.2 | length 60.6
  Top Layer w15: R42.2@4311.47,5040.88 4316.17,5045.57 LED22.1@4316.17,5099.52
$2N2312: LED23.1 R43.2 | length 72.7
  Top Layer w15: LED23.1@4461.01,5105.86 4466.64,5100.23 R43.2@4466.64,5035.49
$2N6344: R44.2 SW9.1 SW9.2 | length 315.1
  Top Layer w15: SW9.1@3671.62,5614.95 3913.7,5614.95 SW9.2@3918.86,5620.12 ; R44.2@3795.47,5673.13 3795.47,5637.94 3817.05,5616.36
$2N6348: R45.2 SW8.1 SW8.2 | length 436
  Top Layer w15: SW8.2@3935.13,5283.95 4049.13,5283.95 R45.2@4083.96,5318.78
  Bottom Layer w15: SW8.1@3651.18,5286.85 3917.18,5286.85 SW8.2@3921.93,5282.1
$2N6353: R46.2 SW7.1 SW7.2 | length 706.2
  Top Layer w9: SW7.2@3932.98,4948.42 3932.98,4895.41 3984.17,4844.21 3984.17,4730.68 4046.69,4668.17 R46.2@4176.82,4668.17
  Bottom Layer w15: SW7.1@3668.59,4943.26 3906.1,4943.26 SW7.2@3914.02,4951.18
$2N6358: R49.2 SW5.1 SW5.2 | length 519.8
  Top Layer w9: SW5.2@3933.75,4303.39 3970.69,4340.34 R49.2@4190.25,4340.34
  Bottom Layer w15: SW5.1@3677.3,4287.75 3921.93,4287.75 SW5.2@3924.31,4290.13
$2N6363: R48.2 SW6.1 SW6.2 | length 1099.6
  Top Layer w9: SW6.2@3912.52,4597.17 3912.52,4543.55 3856.37,4487.4 3856.37,4331.87 3845.87,4321.37 3845.87,4254.85 3893.4,4207.32 3960.32,4207.32 4032.98,4134.66 4134.27,4134.66 4153.19,4115.73 4153.19,4075.71 4177.47,4051.43 R48.2@4177.47,4014.49
  Bottom Layer w15: SW6.1@3670.18,4625.01 3912.43,4625.01 SW6.2@3920.35,4617.09
$2N6573: D1.2 SW9.3 | length 899.6
  Top Layer w9: SW9.3@3673.95,5414.28 3673.95,5389.01 3748.37,5314.6 3748.37,5183.17 3898.85,5032.69 3948.93,5032.69 4007.34,4974.29 4007.34,4785.77 4040.02,4753.08 D1.2@4097.41,4753.08
$2N6576: D2.2 SW8.3 | length 942.2
  Top Layer w9: SW8.3@3652.55,5106.82 3652.55,5082.89 3842.55,4892.89 3842.55,4753.79 3896.86,4699.48 3960.13,4699.48 3998.13,4661.48 3998.13,4456.29 4030.85,4423.57 D2.2@4096,4423.57
$2N6578: D3.2 SW7.3 | length 949.8
  Top Layer w9: SW7.3@3677.32,4771.73 3677.32,4719.45 3742.57,4654.2 3742.57,4285.3 3843.65,4184.22 3956.78,4184.22 4053.42,4087.58 4094.67,4087.58 D3.2@4096.31,4085.94
$2N6580: D5.2 SW5.3 | length 388.2
  Top Layer w9: SW5.3@3668.83,4115 3809.22,4115 D5.2@3984.45,3939.77
$2N6582: D4.2 SW6.3 | length 851.6
  Top Layer w9: SW6.3@3670.94,4444.34 3726.81,4388.47 3726.81,4228.49 3962.45,3992.85 4120.21,3992.85 4186.67,3926.39 4210.31,3926.39 4210.31,3923.97 D4.2@4211.4,3922.88
+3.3V: H1.1 H1.17 R3.1 R4.1 R7.2 R8.2 R11.1 R12.1 R15.2 R16.2 R44.1 R45.1 R46.1 R48.1 R49.1 R50.2 R51.2 R52.2 R53.2 | length 2500.8
  Top Layer w15: R44.1@3840.98,5666.56 3840.98,5690.7 3897.77,5747.49 H1.1@3912.55,5747.49 ; v1@4129.02,5351.09 4131.36,5348.74 R45.1@4131.36,5317.78 ; R46.1@4222.87,4668.81 4267.51,4668.81 v1(4282.63,4653.69) ; R48.1@4225.64,4011.73 4266.77,4011.73 v1(4278.46,4000.04) ; R49.1@4227.13,4338.8 4227.13,4324.87 v1(4268.93,4283.08) ; R50.2@4888.74,5632.41 4889.83,5633.5 4966.32,5633.5 v1@5033.12,5566.7 ; v1(5030.91,4631.92) 5075.47,4676.49 5075.47,4692.72 R52.2@5075.11,4693.09 ; v1@5033.12,5565.3 v1@5033.12,5566.7 ; v1(5047.87,4141.68) 5047.87,4129.83 R11.1@5080.16,4097.53 ; R4.1@5072.53,5575.62 5063.61,5566.7 v1@5033.12,5566.7 ; v1(5127.28,4893.43) 5127.28,4973.49 R3.1@5169.67,5015.87 ; R12.1@5233.1,4667.23 5233.1,4633.57 v1(5248.51,4618.16) ; v1(5377.35,4619.1) 5377.35,4657.48 R53.2@5383.82,4663.94 ; R51.2@5461.94,5016.22 5677.85,5232.13 v1(5761.36,5232.13) ; v1(5643.89,5667.39) 5643.89,5663.34 R7.2@5675.69,5631.53 ; v1@5837.28,4086.06 5837.28,4095.66 5850.48,4108.86 5850.48,4124.59 R15.2@5856.51,4130.63 ; v1@5887.01,4666.62 5903.19,4682.81 R16.2@5903.19,4727.85 ; v1(5936.44,5539.51) 5951.01,5539.51 5957.86,5546.36 R8.2@5957.86,5601.71
  Inner2 w37: H1.1@3925.36,5756.32 3925.36,5738.72 4036.04,5628.04 4601.43,5628.04 4721.26,5747.87 H1.17@4721.26,5754.21
  other v1: 5834.23,4085.47 5885.74,4666.02 4130.42,5354.84 5030.3,5564.83
+5V: H1.2 H1.4 LED1.2 LED2.2 LED3.2 LED4.2 LED5.2 LED6.2 LED7.2 LED8.2 LED9.2 LED10.2 LED11.2 LED12.2 LED13.2 LED14.2 LED15.2 | length 243.7
  Top Layer w20: v1(4021.83,4224.27) 4053.93,4192.17 LED11.2@4053.93,4186.53 ; v1(4042.38,4470.07) 4055.49,4483.18 LED6.2@4055.49,4513.96
  Top Layer w30: LED1.2@4058.46,4847.29 4058.46,4900.54 4103.95,4946.03 v1(4129.72,4946.03)
  other v1: 5571.98,3883.55 4737.46,3892.03 5584.09,3984.27 4735.83,3999.21 5575.13,4093.58 4729.31,4137.12 5594.72,4694.76 4723.94,4788.27 4728.87,4890.3 5594.64,4892.59 4723.24,4986.71 5595.35,5003
ALL_ROOM_LED: H1.18 R18.1 | length 1173.1
  Top Layer w15: R18.1@4475.37,4916.75 4468.5,4916.75 4462.99,4911.24 4482.52,4911.24 4490.95,4902.81 4543.8,4902.81 v1(4554.26,4892.36)
  Bottom Layer w9: v1(4554.26,4892.36) 4554.26,4921.6 4705.47,5072.82 4705.47,5663.18 4672.24,5696.41 4672.24,5806.51 4705.47,5839.74 4705.47,5852.53 H1.18@4711.8,5858.86
CLK_BASS: H1.29 R11.2 SW3.A | length 1851
  Top Layer w15: R11.2@5130.3,4102.93 5130.3,4235.7 SW3.A@5178.62,4284.02
  Bottom Layer w9: SW3.A@5194.65,4278.47 5202.4,4278.47 5255.51,4331.59 5255.51,4525.64 5191.97,4589.18 5191.97,4726.76 5316.4,4851.19 5344.65,4851.19 5383.67,4890.2 5383.67,5081.28 5347.13,5117.82 5347.13,5709.69 H1.29@5310.73,5746.09
CLK_EXTRA: H1.38 R15.1 SW4.A | length 2242.5
  Top Layer w9: R15.1@5906.32,4132.26 5906.32,4119.53 5936.36,4089.49 5992.86,4089.49 v1@5997.9,4084.46
  Top Layer w15: R15.1@5896.56,4139.42 5904.19,4131.8 6034.49,4262.1 SW4.A@6034.49,4275.24
  Bottom Layer w9: H1.38@5711.39,5844.89 5671.98,5805.48 5671.98,5705.14 5833.74,5543.37 5833.74,4286.15 5996.74,4123.15 v1@5996.74,4080.23
  other v1: 5996.58,4085.97
CLK_TREB: H1.40 R7.1 SW2.A | length 1018.7
  Top Layer w15: R7.1@5720.73,5628.72 5721.4,5629.39 R7.1@5734,5629.39 ; R7.1@5733.56,5629.82 R7.1@5734,5629.39 ; v1@5908.6,5696.54 5908.6,5693.71 5840.91,5626.02 5785.19,5626.02 ; SW2.A@6032.29,5181.63 5866.2,5347.72 5866.2,5545 5785.19,5626.02 ; R7.1@5734,5629.39 5781.81,5629.39 5785.19,5626.02 ; R7.1@5734,5629.39 5737.37,5626.02 5785.19,5626.02
  Bottom Layer w9: H1.40@5827.97,5857.11 5884.73,5800.35 5884.73,5715.43 v1@5908.19,5691.98
  other v1: 5907.71,5695.43
CLK_VOL: H1.27 R3.2 SW1.A | length 840.9
  Top Layer w15: SW1.A@5180.91,5185.01 5230.67,5185.01 v1(5275.35,5229.69) ; SW1.A@5186.56,5165.06 5219.87,5131.75 R3.2@5219.87,5018.69
  Bottom Layer w9: H1.27@5221.43,5772.97 5224.13,5770.27 5224.13,5629.35 5277.92,5575.55 5277.92,5232.27 v1(5275.35,5229.69)
DT_BASS: H1.32 R12.2 SW3.B | length 1503.6
  Top Layer w9: SW3.B@5175.75,4496.35 5175.75,4651.21 R12.2@5191.03,4666.5 ; R12.2@5189.41,4669.26 5198.41,4678.26 5198.41,4712.31 5273.85,4787.75 5273.85,4928.8 5366.91,5021.86 5366.91,5415.84 5486.93,5535.86 5486.93,5673.28 5471.84,5688.37 5471.84,5812.08 H1.32@5433.1,5850.82
DT_EXTRA: H1.28 R16.1 SW4.B | length 1998.6
  Top Layer w9: H1.28@5235.44,5873.84 5272.79,5911.19 5550.13,5911.19 5572.55,5888.76 5572.55,5655.41 5625.8,5602.16 5625.8,5465.95 5950.18,5141.57 5950.18,4887.34 6001.79,4835.73 6001.79,4774.98 R16.1@5953.87,4727.06 ; R16.1@5950.28,4732.22 5951.84,4730.66 5951.84,4626.76 6030.63,4547.97 SW4.B@6030.63,4488.15
DT_TREB: H1.37 R8.1 SW2.B | length 714
  Top Layer w9: 5999.5,5559.02 5999.5,5405.91 6012.46,5392.94 SW2.B@6020.14,5392.94 ; R8.1@6003.19,5609.8 6059.96,5609.8 v1(6069.24,5600.51)
  Top Layer w15: R8.1@5998.09,5603.59 5998.56,5603.12 5998.56,5562.78
  Bottom Layer w9: H1.37@5721.47,5754.37 5721.47,5733.16 5854.12,5600.51 v1(6069.24,5600.51)
DT_VOL: H1.21 R4.2 SW1.B | length 483.9
  Top Layer w9: H1.21@4926.1,5736.97 4926.1,5720.78 4959.82,5687.06 5041.27,5687.06 5121.54,5606.78 R4.2@5121.54,5571.07
  Top Layer w15: R4.2@5122.25,5574.21 5170.58,5525.89 SW1.B@5170.58,5404.85
GND: H1.6 H1.9 H1.14 H1.20 H1.25 H1.30 H1.34 H1.39 Q1.2 Q2.2 Q3.2 R36.1 R37.1 R38.1 R39.1 R40.1 R41.1 R42.1 R43.1 SW1.2 SW1.C SW2.2 SW2.C SW3.2 SW3.C SW4.2 SW4.C SW5.5 SW6.5 SW7.5 SW8.5 SW9.5
  other v1: 5007.7,3890.18 5313.75,4124.8 6073.56,4169.46 5602.54,4300.64 5277.31,4710.65 6067.86,4887.8 4109.72,5024.64 4409.66,5036.51 4566.75,5038.8 4255.84,5053.5 5278.85,5070.98 5596.99,5264.54 4480.53,5322.46 4359.49,5327.62 4230.28,5333.31 4105.36,5391.24 5222,5537.28 5979.7,5660.55 5535.95,5666.64
  other v2: 4388.15,4182.97 4424.07,4530.1 4284.2,4593.83 4405.27,4861.81
  other v3: 4161.63,4236.06
ROOM1_LED: H1.3 LED20.2 | length 960.7
  Top Layer w12: H1.3@4026.73,5749.12 4033.85,5742 4033.85,5589.83 3955.29,5511.26 3895.97,5511.26 3860.08,5475.37 3860.08,5321.96 3831.54,5293.42 3831.54,5227.25 3869.54,5189.25 4034.21,5189.25 4074.32,5149.14 LED20.2@4074.32,5106.91
ROOM2_LED: H1.8 LED21.2 | length 795
  Top Layer w12: LED21.2@4227.29,5106.28 4227.29,5168.38 4276.37,5217.46 4276.37,5791.77 4228.35,5839.8 H1.8@4228.35,5861.01
ROOM3_LED: H1.11 LED22.2 | length 682.4
  Top Layer w12: LED22.2@4363.46,5101 4425.74,5163.28 H1.11@4425.74,5757.57
ROOM4_LED: H1.13 LED23.2 | length 683.5
  Top Layer w12: LED23.2@4516.52,5101 4522.85,5107.33 4522.85,5265.05 4549.68,5291.88 4549.68,5703.42 4522.85,5730.24 H1.13@4522.85,5759.68
SINGLE_ROOM_LED: H1.24 R30.1 | length 1842.3
  Top Layer w15: R30.1@4484.98,4280.18 4526.38,4321.57 v1(4526.38,4331.13)
  Bottom Layer w9: v1(4526.38,4331.13) 4580.55,4385.31 4630.63,4385.31 4730.56,4485.25 4730.56,4666.96 5003.46,4939.86 5003.46,5515.94 4972.12,5547.27 4972.12,5807.87 H1.24@5012.82,5848.57
SINGLE_SPK_LED: H1.22 R24.1 | length 1425.3
  Top Layer w15: R24.1@4469.15,4639.07 4485.85,4639.07 v1(4504.32,4657.54)
  Bottom Layer w9: v1(4504.32,4657.54) 4625.03,4778.25 4646.46,4778.25 4702.66,4834.45 4743.28,4834.45 4785.43,4876.6 4785.43,5629.99 4871.77,5716.33 4871.77,5790.56 H1.22@4914.83,5833.62
SPK1_LED: H1.5 LED16.2 | length 340.6
  Top Layer w12: LED16.2@4071.07,5434.56 4118.57,5482.06 H1.5@4118.57,5755.46
SPK2_LED: H1.7 LED17.2 | length 316.6
  Top Layer w12: LED17.2@4220.96,5435.62 4220.96,5741.73 H1.7@4228.35,5749.12
SPK3_LED: H1.10 LED18.2 | length 429.2
  Top Layer w12: H1.10@4321.24,5848.35 4321.24,5844.99 4369.84,5796.39 4369.84,5449.67 4363.46,5443.29 LED18.2@4363.46,5441.95
SPK4_LED: H1.12 LED19.2 | length 453.6
  Top Layer w12: H1.12@4429.96,5845.18 4472.45,5802.69 4472.45,5702.77 4516.17,5659.05 4516.17,5441.25 LED19.2@4526.02,5431.39
SW_ALL_ROOM: D1.1 H1.16 | length 1402.6
  Top Layer w15: D1.1@4219.78,4746.53 4252.92,4713.4 v1(4269.69,4713.4)
  Bottom Layer w9: v1@4268.11,4710.34 4192.11,4786.34 4192.11,5348.7 4571.98,5728.57 4571.98,5797.18 4611.7,5836.9 H1.16@4611.7,5844.03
